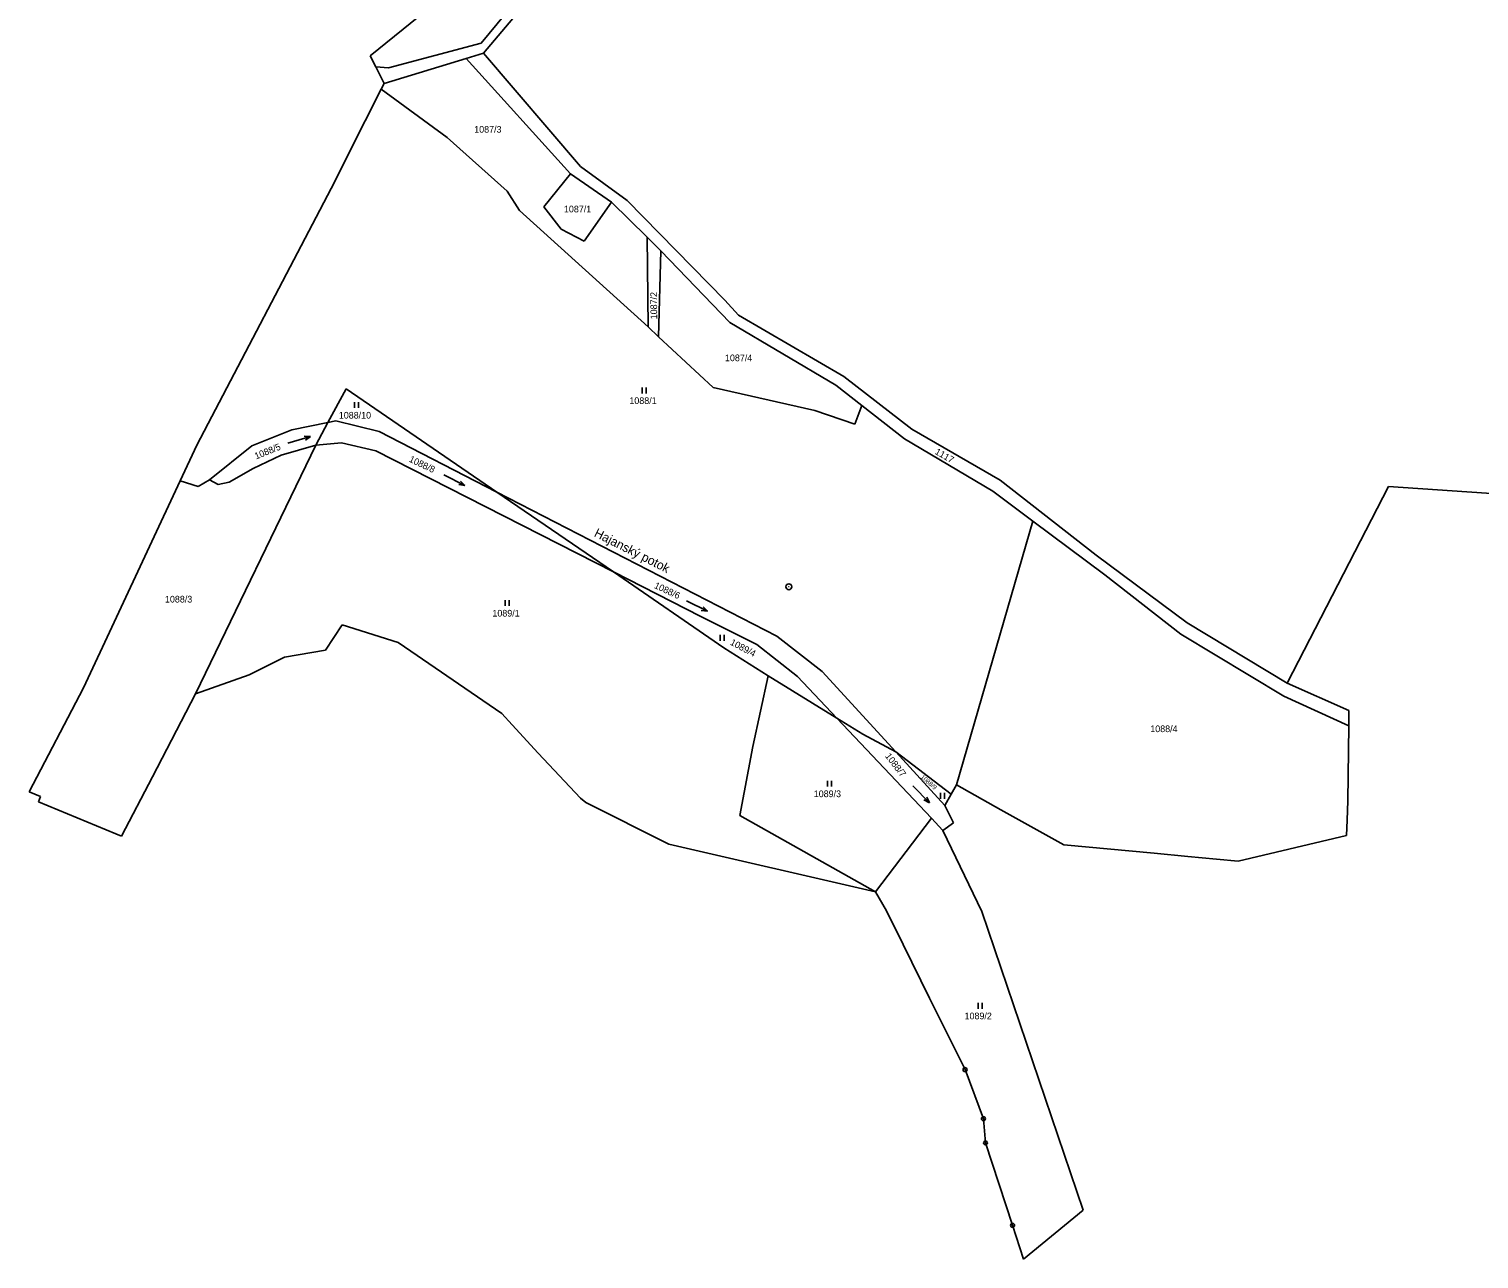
# Model space of a CAD drawing. Extents: x -794142 to -791199, y -1109267 to -1105626.
# Drawn here: x -793399.5 to -793029.9, y -1109224.1 to -1108910.4 of the extents above; entities that cross this region are included whole.
import ezdxf

# ---------------------------------------------------------------- set-up
doc = ezdxf.new("R2010")
doc.units = 0
for name, color, linetype in [('Vrstva 1', 7, 'Continuous'), ('Vrstva 14', 7, 'Continuous'), ('Vrstva 23', 7, 'Continuous'), ('Vrstva 28', 7, 'Continuous'), ('Vrstva 4', 7, 'Continuous'), ('Vrstva 44', 7, 'Continuous')]:
    doc.layers.add(name, color=color, linetype=linetype)

msp = doc.modelspace()

# ---------------------------------------------------------------- linework, layer by layer
at = {"layer": 'Vrstva 1'}
for p, q in [((-793283.66, -1108916.62), (-793251.19, -1108877.99)), ((-793268.35, -1108894.78), (-793284.31, -1108914.01)), ((-793284.31, -1108914.01), (-793307.93, -1108920.35)), ((-793309, -1108924.32), (-793288.11, -1108917.97)), ((-793288.11, -1108917.97), (-793283.66, -1108916.62)), ((-793288.11, -1108917.97), (-793261.46, -1108947.4)), ((-793283.66, -1108916.62), (-793258.97, -1108945.5)), ((-793307.93, -1108920.35), (-793311.11, -1108920.11)), ((-793309.72, -1108925.73), (-793292.98, -1108938.1)), ((-793292.98, -1108938.1), (-793277.64, -1108951.81)), ((-793261.46, -1108947.4), (-793268.26, -1108955.76)), ((-793261.46, -1108947.4), (-793251.08, -1108954.62)), ((-793258.97, -1108945.5), (-793247.04, -1108954.18)), ((-793277.64, -1108951.81), (-793274.5, -1108956.72)), ((-793258.04, -1108964.56), (-793251.08, -1108954.62)), ((-793251.08, -1108954.62), (-793241.97, -1108963.52)), ((-793247.04, -1108954.18), (-793222.16, -1108979.53)), ((-793274.5, -1108956.72), (-793241.73, -1108986.41)), ((-793268.26, -1108955.76), (-793263.87, -1108961.49)), ((-793263.87, -1108961.49), (-793258.04, -1108964.56)), ((-793241.97, -1108963.52), (-793238.46, -1108966.95)), ((-793241.97, -1108963.52), (-793241.73, -1108986.41)), ((-793238.46, -1108966.95), (-793239.04, -1108988.88)), ((-793238.46, -1108966.95), (-793220.89, -1108985.27)), ((-793222.16, -1108979.53), (-793218.69, -1108983.42)), ((-793218.69, -1108983.42), (-793191.84, -1108999.03)), ((-793241.73, -1108986.41), (-793239.04, -1108988.88)), ((-793239.04, -1108988.88), (-793225.16, -1109001.88)), ((-793220.89, -1108985.27), (-793193.89, -1109001.23)), ((-793191.84, -1108999.03), (-793174.5, -1109012.48)), ((-793323.32, -1109010.76), (-793318.68, -1109002.21)), ((-793318.68, -1109002.21), (-793280.24, -1109028.54)), ((-793225.16, -1109001.88), (-793199.18, -1109007.71)), ((-793193.89, -1109001.23), (-793187.24, -1109006.43)), ((-793189.06, -1109011.19), (-793187.24, -1109006.43)), ((-793187.24, -1109006.43), (-793176.34, -1109014.95)), ((-793323.32, -1109010.76), (-793332.5, -1109012.61)), ((-793326.45, -1109016.53), (-793323.32, -1109010.76)), ((-793321.35, -1109010.36), (-793323.32, -1109010.76)), ((-793310.31, -1109013.08), (-793321.35, -1109010.36)), ((-793199.18, -1109007.71), (-793189.06, -1109011.19)), ((-793332.5, -1109012.61), (-793342.77, -1109016.71)), ((-793280.24, -1109028.54), (-793310.31, -1109013.08)), ((-793174.5, -1109012.48), (-793151.97, -1109025.44)), ((-793357.12, -1109079.92), (-793326.45, -1109016.53)), ((-793342.77, -1109016.71), (-793353.52, -1109025.37)), ((-793335.22, -1109019.13), (-793326.45, -1109016.53)), ((-793326.45, -1109016.53), (-793319.88, -1109015.96)), ((-793319.88, -1109015.96), (-793311.14, -1109017.97)), ((-793311.14, -1109017.97), (-793250.56, -1109048.88)), ((-793176.34, -1109014.95), (-793153.87, -1109028.29)), ((-793342.37, -1109022.51), (-793335.22, -1109019.13)), ((-793356.38, -1109027.11), (-793360.97, -1109025.63)), ((-793353.52, -1109025.37), (-793356.38, -1109027.11)), ((-793353.52, -1109025.37), (-793351.27, -1109026.6)), ((-793348.47, -1109025.95), (-793342.37, -1109022.51)), ((-793151.97, -1109025.44), (-793127.47, -1109044.6)), ((-793351.27, -1109026.6), (-793348.47, -1109025.95)), ((-793208.91, -1109065.23), (-793280.24, -1109028.54)), ((-793280.24, -1109028.54), (-793250.56, -1109048.88)), ((-793143.65, -1109035.92), (-793153.87, -1109028.29)), ((-793143.65, -1109035.92), (-793163.12, -1109103.18)), ((-793125.31, -1109049.59), (-793143.65, -1109035.92)), ((-793127.47, -1109044.6), (-793104.29, -1109061.87)), ((-793250.56, -1109048.88), (-793222.38, -1109068.19)), ((-793250.56, -1109048.88), (-793228.3, -1109060.24)), ((-793125.31, -1109049.59), (-793105.93, -1109064.77)), ((-793228.3, -1109060.24), (-793213.98, -1109067.4)), ((-793104.29, -1109061.87), (-793078.8, -1109077.2)), ((-793197.36, -1109074.23), (-793208.91, -1109065.23)), ((-793105.93, -1109064.77), (-793079.68, -1109080.51)), ((-793222.38, -1109068.19), (-793211.15, -1109075.38)), ((-793213.98, -1109067.4), (-793203.65, -1109075.49)), ((-793211.15, -1109075.38), (-793215.03, -1109093.34)), ((-793211.15, -1109075.38), (-793193.58, -1109086.16)), ((-793193.58, -1109086.16), (-793203.65, -1109075.49)), ((-793178.61, -1109094.75), (-793197.36, -1109074.23)), ((-793079.68, -1109080.51), (-793063.11, -1109088.09)), ((-793193.58, -1109086.16), (-793186.95, -1109090.22)), ((-793169.51, -1109111.65), (-793193.58, -1109086.16)), ((-793186.95, -1109090.22), (-793178.61, -1109094.75)), ((-793215.03, -1109093.34), (-793218.3, -1109110.97)), ((-793178.61, -1109094.75), (-793166.04, -1109108.42)), ((-793178.61, -1109094.75), (-793164.44, -1109105.56)), ((-793183.76, -1109130.47), (-793218.3, -1109110.97)), ((-793183.76, -1109130.47), (-793169.51, -1109111.65)), ((-793166.58, -1109114.75), (-793169.51, -1109111.65))]:
    msp.add_line(p, q, dxfattribs=at)
at = {"layer": 'Vrstva 23'}
for p, q in [((-793243.25, -1109003.35), (-793243.25, -1109001.85)), ((-793242.25, -1109001.85), (-793242.25, -1109003.35)), ((-793316.56, -1109007.06), (-793316.56, -1109005.56)), ((-793315.56, -1109005.56), (-793315.56, -1109007.06)), ((-793333.511, -1109016.069), (-793327.768, -1109014.33)), ((-793327.768, -1109014.33), (-793329.349, -1109014.286)), ((-793327.768, -1109014.33), (-793329.059, -1109015.243)), ((-793293.789, -1109024.14), (-793288.43, -1109026.839)), ((-793288.43, -1109026.839), (-793289.545, -1109025.718)), ((-793288.43, -1109026.839), (-793289.995, -1109026.611)), ((-793278.14, -1109057.54), (-793278.14, -1109056.04)), ((-793277.14, -1109056.04), (-793277.14, -1109057.54)), ((-793231.969, -1109056.2), (-793226.61, -1109058.899)), ((-793226.61, -1109058.899), (-793228.175, -1109058.671)), ((-793226.61, -1109058.899), (-793227.725, -1109057.778)), ((-793223.37, -1109066.43), (-793223.37, -1109064.93)), ((-793222.37, -1109064.93), (-793222.37, -1109066.43)), ((-793195.98, -1109103.59), (-793195.98, -1109102.09)), ((-793194.98, -1109102.09), (-793194.98, -1109103.59)), ((-793174.196, -1109103.423), (-793169.983, -1109107.696)), ((-793169.983, -1109107.696), (-793171.393, -1109106.979)), ((-793169.983, -1109107.696), (-793170.68, -1109106.277)), ((-793167.15, -1109106.69), (-793167.15, -1109105.19)), ((-793166.15, -1109105.19), (-793166.15, -1109106.69)), ((-793157.56, -1109160.22), (-793157.56, -1109158.72)), ((-793156.56, -1109158.72), (-793156.56, -1109160.22))]:
    msp.add_line(p, q, dxfattribs=at)
at = {"layer": 'Vrstva 28'}
for centre, radius in [((-793205.85, -1109052.64), 0.75), ((-793205.85, -1109052.64), 0.01), ((-793160.93, -1109175.76), 0.5), ((-793160.93, -1109175.76), 0.01), ((-793156.25, -1109188.28), 0.5), ((-793156.25, -1109188.28), 0.5), ((-793156.25, -1109188.28), 0.01), ((-793156.25, -1109188.28), 0.01), ((-793155.72, -1109194.45), 0.5), ((-793155.72, -1109194.45), 0.5), ((-793155.72, -1109194.45), 0.01), ((-793155.72, -1109194.45), 0.01), ((-793148.81, -1109215.46), 0.5), ((-793148.81, -1109215.46), 0.01)]:
    msp.add_circle(centre, radius, dxfattribs=at)
at = {"layer": 'Vrstva 4'}
for p, q in [((-793284.27, -1108894.3), (-793312.56, -1108917.24)), ((-793312.56, -1108917.24), (-793311.11, -1108920.11)), ((-793311.11, -1108920.11), (-793309, -1108924.32)), ((-793309.72, -1108925.73), (-793313.87, -1108933.82)), ((-793309, -1108924.32), (-793309.72, -1108925.73)), ((-793322.52, -1108951.07), (-793313.87, -1108933.82)), ((-793356.73, -1109016.56), (-793322.52, -1108951.07)), ((-793360.97, -1109025.63), (-793356.73, -1109016.56)), ((-793385.67, -1109078.43), (-793360.97, -1109025.63)), ((-793078.8, -1109077.2), (-793053.03, -1109027.09)), ((-793053.03, -1109027.09), (-793024.23, -1109029.05)), ((-793319.71, -1109062.38), (-793323.97, -1109068.82)), ((-793305.45, -1109066.88), (-793319.71, -1109062.38)), ((-793323.97, -1109068.82), (-793334.37, -1109070.57)), ((-793294.39, -1109074.43), (-793305.45, -1109066.88)), ((-793334.37, -1109070.57), (-793343.38, -1109075.14)), ((-793357.12, -1109079.92), (-793343.38, -1109075.14)), ((-793290.02, -1109077.42), (-793294.39, -1109074.43)), ((-793279.02, -1109084.94), (-793290.02, -1109077.42)), ((-793078.8, -1109077.2), (-793063.06, -1109084.19)), ((-793385.67, -1109078.43), (-793399.53, -1109104.93)), ((-793368.09, -1109101.13), (-793357.12, -1109079.92)), ((-793276.41, -1109087.86), (-793279.02, -1109084.94)), ((-793063.11, -1109088.09), (-793063.06, -1109084.19)), ((-793276.41, -1109087.86), (-793269.72, -1109095.04)), ((-793063.38, -1109107.22), (-793063.11, -1109088.09)), ((-793269.72, -1109095.04), (-793258.98, -1109106.56)), ((-793375.92, -1109116.27), (-793368.09, -1109101.13)), ((-793163.12, -1109103.18), (-793164.44, -1109105.56)), ((-793163.12, -1109103.18), (-793151.82, -1109109.48)), ((-793399.53, -1109104.93), (-793396.59, -1109106.14)), ((-793396.59, -1109106.14), (-793397.14, -1109107.48)), ((-793257.6, -1109107.66), (-793258.98, -1109106.56)), ((-793164.44, -1109105.56), (-793166.04, -1109108.42)), ((-793397.14, -1109107.48), (-793377.4, -1109115.66)), ((-793236.44, -1109118.27), (-793257.6, -1109107.66)), ((-793166.04, -1109108.42), (-793163.88, -1109112.85)), ((-793135.77, -1109118.42), (-793151.82, -1109109.48)), ((-793063.54, -1109112.17), (-793063.38, -1109107.22)), ((-793166.58, -1109114.75), (-793163.88, -1109112.85)), ((-793063.66, -1109116.09), (-793063.54, -1109112.17)), ((-793377.4, -1109115.66), (-793375.92, -1109116.27)), ((-793183.76, -1109130.47), (-793236.44, -1109118.27)), ((-793166.58, -1109114.75), (-793156.64, -1109135.42)), ((-793091.27, -1109122.62), (-793063.66, -1109116.09)), ((-793135.77, -1109118.42), (-793112.76, -1109120.59)), ((-793112.76, -1109120.59), (-793104.11, -1109121.41)), ((-793104.11, -1109121.41), (-793096.81, -1109122.1)), ((-793096.81, -1109122.1), (-793091.27, -1109122.62)), ((-793180.95, -1109135.24), (-793183.76, -1109130.47)), ((-793176.71, -1109143.82), (-793180.95, -1109135.24)), ((-793130.85, -1109211.63), (-793156.64, -1109135.42)), ((-793169.95, -1109157.5), (-793176.71, -1109143.82)), ((-793160.93, -1109175.76), (-793169.95, -1109157.5)), ((-793156.25, -1109188.28), (-793160.93, -1109175.76)), ((-793155.72, -1109194.45), (-793156.25, -1109188.28)), ((-793148.81, -1109215.46), (-793155.72, -1109194.45)), ((-793145.99, -1109224.05), (-793130.85, -1109211.63)), ((-793145.99, -1109224.05), (-793148.81, -1109215.46))]:
    msp.add_line(p, q, dxfattribs=at)

# ---------------------------------------------------------------- texts
at = {"layer": 'Vrstva 14'}
for s, p in [('1087/3', (-793286.039, -1108936.86)), ('1087/1', (-793263.172, -1108957.19)), ('1087/4', (-793222.124, -1108995.13)), ('1088/1', (-793246.495, -1109006.05)), ('1088/10', (-793320.554, -1109009.76)), ('1088/3', (-793364.872, -1109056.66)), ('1089/1', (-793281.405, -1109060.24)), ('1088/4', (-793113.708, -1109089.71)), ('1089/3', (-793199.492, -1109106.29)), ('1089/2', (-793161.052, -1109162.92))]:
    msp.add_text(s, height=1.7, dxfattribs=at).set_placement(p)
for s, height, rotation, p in [('1087/2', 1.7, 90.44613, (-793239.398, -1108984.438)), ('1088/5', 1.7, 22.04757, (-793341.625, -1109020.204)), ('1117', 1.7, 330.09651, (-793168.767, -1109018.676)), ('1088/8', 1.7, 334.44, (-793302.823, -1109020.676)), ('1088/6', 1.7, 335.01699, (-793240.338, -1109052.893)), ('1089/4', 1.7, 332.11008, (-793220.975, -1109067.334)), ('1088/7', 1.7, 307.84257, (-793181.411, -1109095.848)), ('1088/9', 1.14, 318.98826, (-793172.36, -1109101.333))]:
    msp.add_text(s, height=height, rotation=rotation, dxfattribs=at).set_placement(p)
at = {"layer": 'Vrstva 44'}
msp.add_text('Hajanský potok', height=2.3, rotation=333.08847, dxfattribs=at).set_placement((-793255.68, -1109039.69))

doc.saveas('drawing.dxf')
